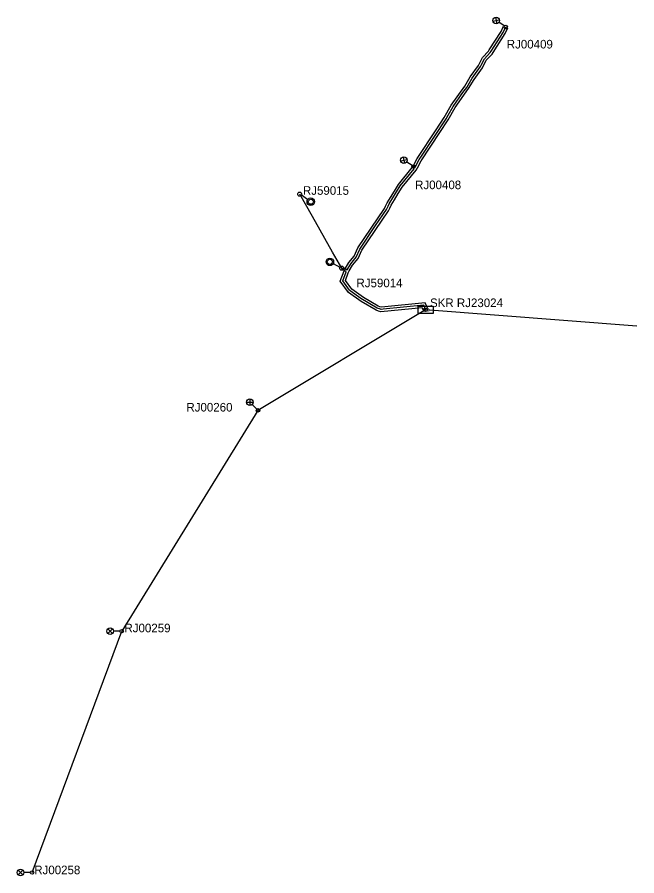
# Model space of a CAD drawing. Extents: x -600701 to -600593, y -1172619 to -1172469.
import ezdxf

# ---------------------------------------------------------------- set-up
doc = ezdxf.new("R2010")
doc.units = 0
for name, color, linetype in [('Chranicka', 7, 'Continuous'), ('Delici_skrin', 7, 'Continuous'), ('Delici_skrin_popis', 7, 'Continuous'), ('Kabelove_vedeni_vrchni', 7, 'Continuous'), ('Kabelove_vedeni_zemni', 7, 'Continuous'), ('Pomocny_stozar', 7, 'Continuous'), ('Prisvetleni_prechodu', 7, 'Continuous'), ('Prisvetleni_prechodu_popis', 7, 'Continuous'), ('Verejne_osvetleni', 7, 'Continuous'), ('Verejne_osvetleni_popis', 7, 'Continuous')]:
    doc.layers.add(name, color=color, linetype=linetype)

msp = doc.modelspace()

# ---------------------------------------------------------------- linework, layer by layer
at = {"layer": 'Chranicka'}
for points in [[(-600630.66, -1172520.25), (-600630.88, -1172519.74), (-600638.11, -1172520.45), (-600638.5, -1172520.32), (-600638.89, -1172520.19), (-600641.54, -1172518.63), (-600643.73, -1172517.1), (-600645.19, -1172515.1), (-600644.51, -1172513.33), (-600644.31, -1172512.94), (-600643.69, -1172511.86), (-600642.76, -1172510.73), (-600642.14, -1172509.32), (-600637.47, -1172502.43), (-600637.27, -1172502.02), (-600636.99, -1172501.45), (-600636.42, -1172500.51), (-600635.74, -1172499.4), (-600635.04, -1172498.25), (-600632.62, -1172495.27), (-600632.42, -1172494.94), (-600631.75, -1172493.7), (-600628.48, -1172488.74), (-600627.05, -1172486.57), (-600625.83, -1172484.42), (-600623.48, -1172481.1), (-600622.52, -1172479.5), (-600621.07, -1172477.5), (-600620.39, -1172476.1), (-600619.34, -1172475.01), (-600619.21, -1172474.8), (-600617.11, -1172471.57), (-600616.7, -1172470.63)], [(-600629.92, -1172519.95), (-600630.36, -1172518.88), (-600638.01, -1172519.63), (-600638.25, -1172519.56), (-600638.55, -1172519.45), (-600641.11, -1172517.95), (-600643.17, -1172516.52), (-600644.29, -1172514.98), (-600643.78, -1172513.66), (-600643.61, -1172513.33), (-600643.03, -1172512.32), (-600642.08, -1172511.15), (-600641.44, -1172509.7), (-600636.77, -1172502.83), (-600636.55, -1172502.36), (-600636.29, -1172501.83), (-600635.73, -1172500.92), (-600635.06, -1172499.82), (-600634.38, -1172498.71), (-600631.96, -1172495.73), (-600631.72, -1172495.33), (-600631.07, -1172494.12), (-600627.82, -1172489.18), (-600626.37, -1172486.99), (-600625.15, -1172484.86), (-600622.8, -1172481.54), (-600621.86, -1172479.94), (-600620.39, -1172477.92), (-600619.73, -1172476.56), (-600618.72, -1172475.51), (-600618.54, -1172475.24), (-600616.41, -1172471.95), (-600615.96, -1172470.95)]]:
    msp.add_lwpolyline(points, dxfattribs=at)
at = {"layer": 'Delici_skrin'}
msp.add_lwpolyline([(-600631.59, -1172519.45), (-600628.99, -1172519.45), (-600628.99, -1172520.75), (-600631.59, -1172520.75)], close=True, dxfattribs=at)
at = {"layer": 'Kabelove_vedeni_vrchni'}
for points in [[(-600644.92, -1172512.84), (-600646.51, -1172510.03), (-600650.03, -1172503.83), (-600652.24, -1172499.94)], [(-600630.29, -1172520.1), (-600659.52, -1172537.64)], [(-600593.49, -1172522.97), (-600630.29, -1172520.1)], [(-600659.52, -1172537.64), (-600683.27, -1172576.13)], [(-600698.89, -1172618.21), (-600683.27, -1172576.13)]]:
    msp.add_lwpolyline(points, dxfattribs=at)
at = {"layer": 'Kabelove_vedeni_zemni'}
for points in [[(-600632.38, -1172495.14), (-600632.07, -1172495.14), (-600631.41, -1172493.91), (-600631.03, -1172493.34), (-600628.86, -1172490.05), (-600626.71, -1172486.78), (-600626.35, -1172486.15), (-600625.49, -1172484.64), (-600623.79, -1172482.23), (-600623.14, -1172481.32), (-600622.19, -1172479.72), (-600620.73, -1172477.71), (-600620.61, -1172477.45), (-600620.06, -1172476.33), (-600619.03, -1172475.26), (-600618.87, -1172475.02), (-600616.76, -1172471.76), (-600616.33, -1172470.79)], [(-600644.92, -1172512.84), (-600644.51, -1172512.76), (-600643.96, -1172513.14), (-600643.36, -1172512.09), (-600642.42, -1172510.94), (-600641.79, -1172509.51), (-600639.13, -1172505.59), (-600639.02, -1172505.43), (-600637.12, -1172502.63), (-600636.84, -1172502.04), (-600636.64, -1172501.64), (-600634.71, -1172498.48), (-600632.29, -1172495.5), (-600632.37, -1172495.36), (-600632.38, -1172495.14)], [(-600630.29, -1172520.1), (-600630.33, -1172520), (-600630.62, -1172519.31), (-600637.7, -1172520), (-600638.06, -1172520.04), (-600638.17, -1172520), (-600638.72, -1172519.82), (-600641.6, -1172518.13), (-600643.45, -1172516.81), (-600643.45, -1172516.8), (-600643.57, -1172516.65), (-600644.74, -1172515.04), (-600644.15, -1172513.5), (-600644.81, -1172513.04), (-600644.92, -1172512.84)]]:
    msp.add_lwpolyline(points, dxfattribs=at)
at = {"layer": 'Pomocny_stozar'}
msp.add_circle((-600630.29, -1172520.1), 0.305, dxfattribs=at)
at = {"layer": 'Prisvetleni_prechodu'}
for p, q in [((-600650.86, -1172500.89), (-600651.95, -1172500.14)), ((-600646.4, -1172512.05), (-600645.23, -1172512.67))]:
    msp.add_line(p, q, dxfattribs=at)
for centre, radius in [((-600652.24, -1172499.94), 0.353), ((-600650.31, -1172501.27), 0.662), ((-600650.31, -1172501.27), 0.441), ((-600646.99, -1172511.74), 0.662), ((-600646.99, -1172511.74), 0.441), ((-600644.92, -1172512.84), 0.353)]:
    msp.add_circle(centre, radius, dxfattribs=at)
at = {"layer": 'Verejne_osvetleni'}
for p, q in [((-600618.57, -1172469.77), (-600617.45, -1172469.55)), ((-600618.12, -1172469.09), (-600617.9, -1172470.22)), ((-600616.58, -1172470.62), (-600617.53, -1172469.98)), ((-600634.64, -1172494.15), (-600633.51, -1172493.91)), ((-600634.19, -1172493.47), (-600633.96, -1172494.59)), ((-600632.64, -1172494.97), (-600633.6, -1172494.34)), ((-600661.51, -1172536.18), (-600660.37, -1172536.19)), ((-600660.93, -1172535.61), (-600660.95, -1172536.76)), ((-600659.74, -1172537.42), (-600660.54, -1172536.6)), ((-600685.7, -1172576.53), (-600684.89, -1172575.72)), ((-600685.7, -1172575.72), (-600684.89, -1172576.53)), ((-600683.57, -1172576.13), (-600684.72, -1172576.13)), ((-600701.32, -1172618.62), (-600700.51, -1172617.81)), ((-600701.32, -1172617.81), (-600700.51, -1172618.62)), ((-600699.19, -1172618.21), (-600700.34, -1172618.21))]:
    msp.add_line(p, q, dxfattribs=at)
for centre, radius in [((-600618.01, -1172469.66), 0.574), ((-600616.33, -1172470.79), 0.306), ((-600634.08, -1172494.03), 0.574), ((-600632.38, -1172495.14), 0.306), ((-600660.94, -1172536.19), 0.574), ((-600659.52, -1172537.64), 0.306), ((-600685.29, -1172576.13), 0.574), ((-600683.27, -1172576.13), 0.306), ((-600700.91, -1172618.21), 0.574), ((-600698.89, -1172618.21), 0.306)]:
    msp.add_circle(centre, radius, dxfattribs=at)

# ---------------------------------------------------------------- texts
at = {"layer": 'Delici_skrin'}
msp.add_text('DS', height=0.65, dxfattribs=at).set_placement((-600630.86, -1172520.43))
at = {"layer": 'Delici_skrin_popis'}
msp.add_text('SKR RJ23024', height=1.5, dxfattribs=at).set_placement((-600629.53, -1172519.63))
at = {"layer": 'Prisvetleni_prechodu_popis'}
for s, p in [('RJ59015', (-600651.68, -1172500.05)), ('RJ59014', (-600642.35, -1172516.17))]:
    msp.add_text(s, height=1.5, dxfattribs=at).set_placement(p)
at = {"layer": 'Verejne_osvetleni_popis'}
for s, p in [('RJ00409', (-600616.15, -1172474.54)), ('RJ00408', (-600632.13, -1172499.07)), ('RJ00260', (-600671.99, -1172537.84)), ('RJ00259', (-600682.79, -1172576.33)), ('RJ00258', (-600698.51, -1172618.51))]:
    msp.add_text(s, height=1.5, dxfattribs=at).set_placement(p)

doc.saveas('drawing.dxf')
